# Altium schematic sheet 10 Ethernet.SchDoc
size 386 x 246 mm
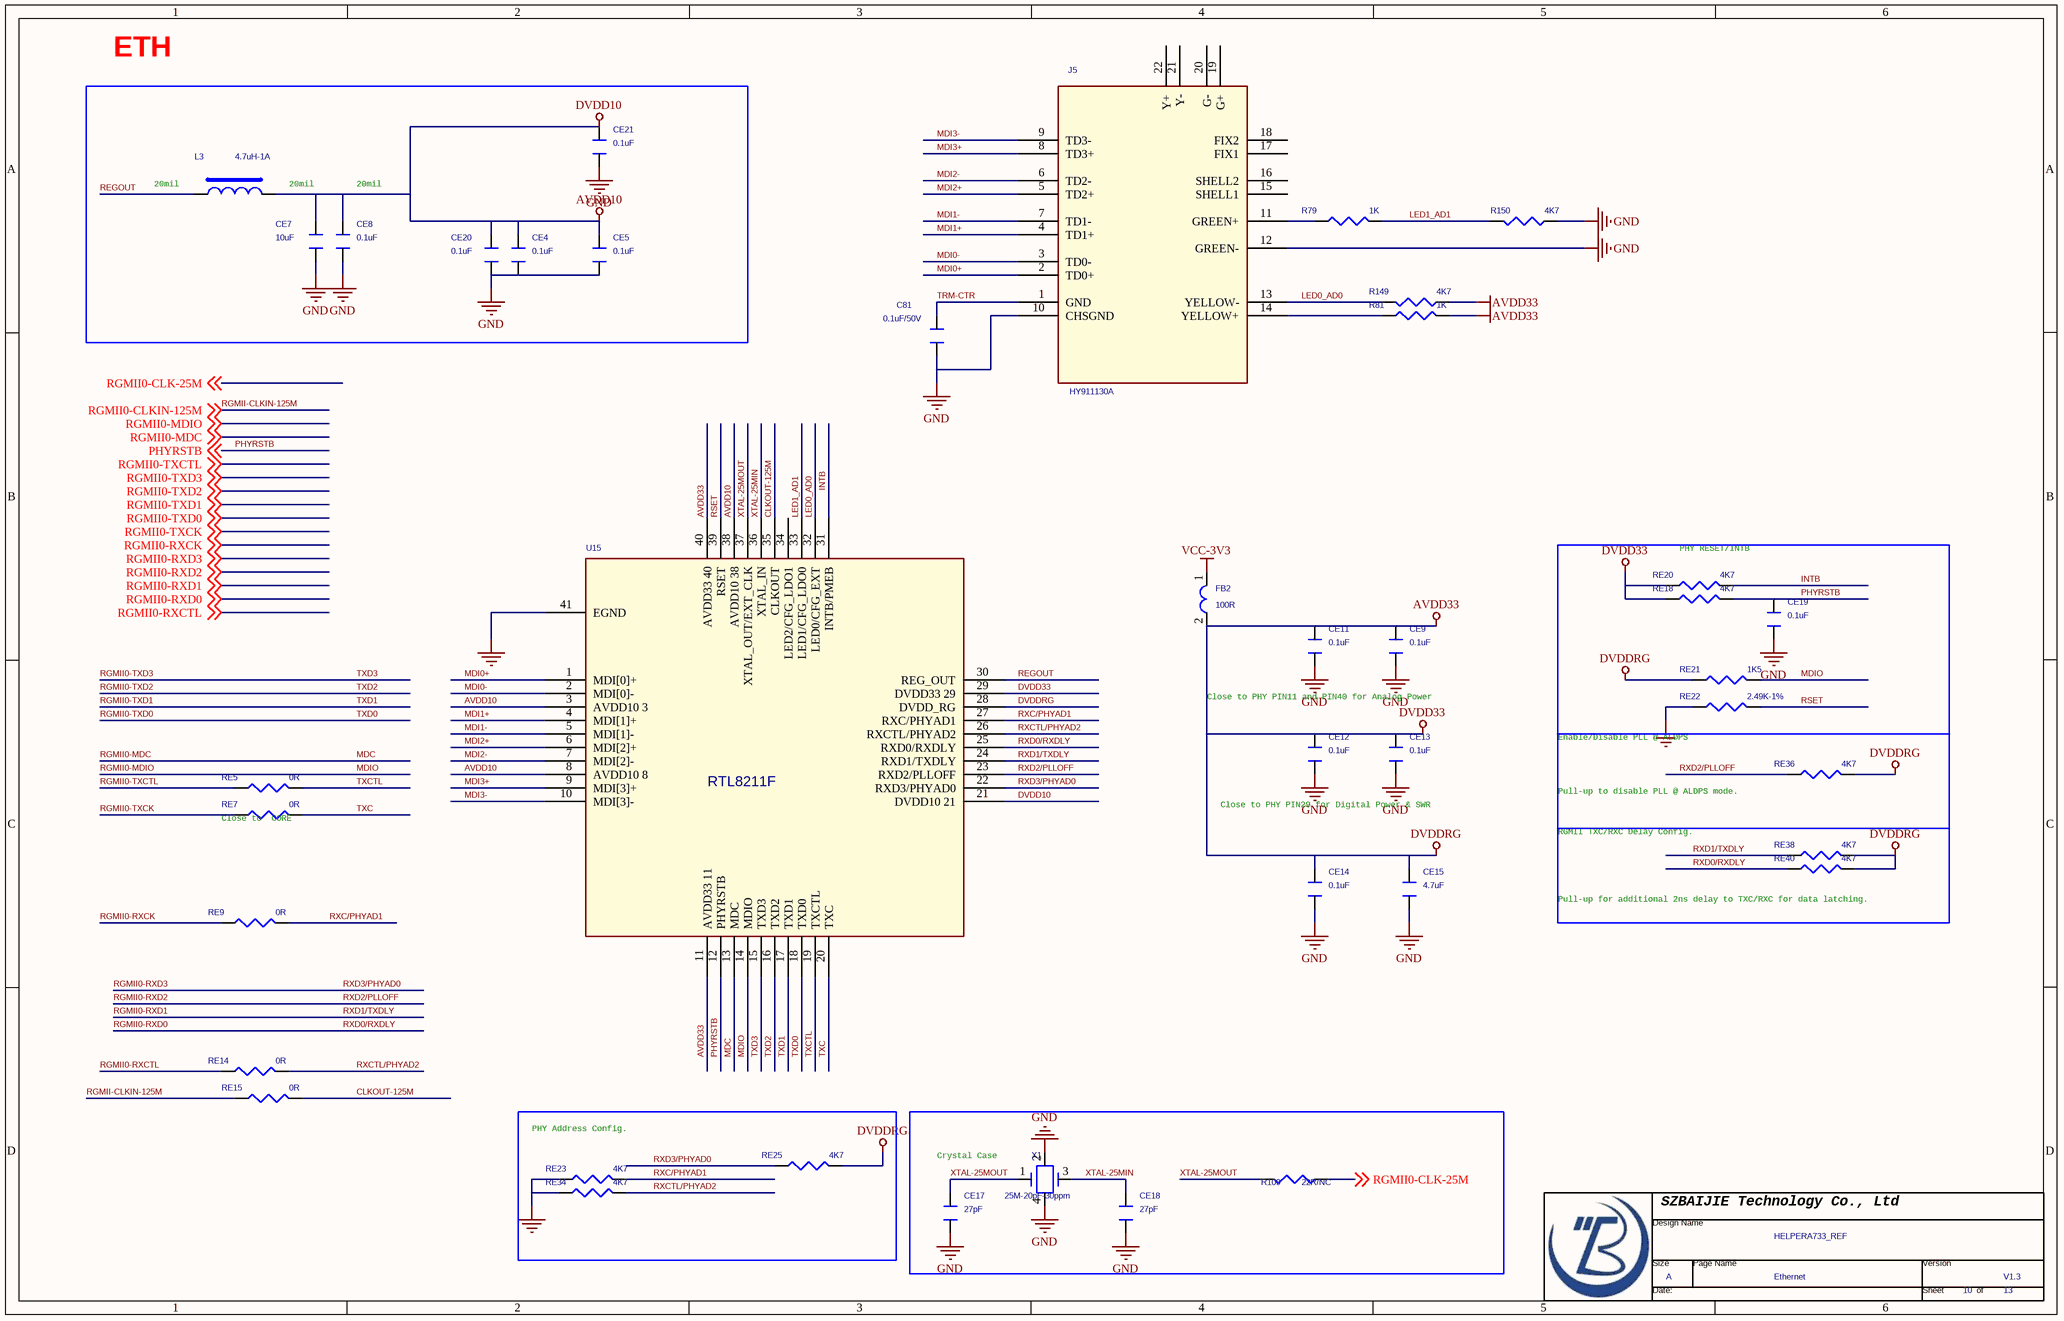
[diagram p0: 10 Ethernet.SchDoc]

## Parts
*  Page Count: 13  Page Number: 10  Page Size: A  Title: HELPERA733_REF  RevCode: V1.3  Doc: Ethernet  (hidden comment: TitleBlock0-BJ)  (graphical)
C81  0.1uF/50V  [C0402]
CE4  0.1uF  [C0402]
CE5  0.1uF  [C0402]
CE7  10uF  [C0402]
CE8  0.1uF  [C0402]
CE9  0.1uF  [C0402]
CE11  0.1uF  [C0402]
CE12  0.1uF  [C0402]
CE13  0.1uF  [C0402]
CE14  0.1uF  [C0402]
CE15  4.7uF  [C0402]
CE17  27pF  [C0402]
CE18  27pF  [C0402]
CE19  0.1uF  [C0402]
CE20  0.1uF  [C0402]
CE21  0.1uF  [C0402]
FB2  100R  [L0603]
J5  HY911130A  [HY911130A]
L3  4.7uH-1A  [LP160_200H100]
R79  1K  [R0402]
R81  1K  [R0402]
R109  22R/NC  [R0402]
R149  4K7  [R0402]
R150  4K7  [R0402]
RE5  0R  [R0402]
RE7  0R  [R0402]
RE9  0R  [R0402]
RE14  0R  [R0402]
RE15  0R  [R0402]
RE18  4K7  [R0402]
RE20  4K7  [R0402]
RE21  1K5  [R0402]
RE22  2.49K-1%  [R0402]
RE23  4K7  [R0402]
RE25  4K7  [R0402]
RE34  4K7  [R0402]
RE36  4K7  [R0402]
RE38  4K7  [R0402]
RE40  4K7  [R0402]
U15  RTL8211F  [QFN40]
X1  25M-20pF-30ppm  [X3225]

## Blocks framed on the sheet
PHY RESET/INTB: CE19 RE18 RE20-RE22
RGMII TXC/RXC Delay Config.: RE38 RE40
PHY Address Config.: RE23 RE25 RE34
Crystal Case: CE17 CE18 R109 X1

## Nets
AVDD10: CE4.2 CE5.2 CE7.2 CE8.2 CE20.2 CE21.2 L3.2 U15.3(AVDD10_3) U15.8(AVDD10_8) U15.21(DVDD10_21) U15.38(AVDD10_38)  [also labelled DVDD10]
AVDD33: CE9.2 CE11.2 CE12.2 CE13.2 CE14.2 CE15.2 FB2.2 R81.2 R149.1 RE18.1 RE20.1 RE21.1 RE25.2 RE36.2 RE38.2 RE40.2 U15.11(AVDD33_11) U15.28(DVDD_RG) U15.29(DVDD33_29) U15.40(AVDD33_40)  [also labelled DVDD33, DVDDRG]
GND: C81.1 CE4.1 CE5.1 CE7.1 CE8.1 CE9.1 CE11.1 CE12.1 CE13.1 CE14.1 CE15.1 CE17.1 CE18.1 CE19.1 CE20.1 CE21.1 J5.10(CHSGND) J5.12(GREEN-) R150.1 RE22.1 RE23.1 RE34.1 U15.41(EGND) X1.2 X1.4
VCC-3V3: FB2.1
CLKOUT-125M: RE15.2 U15.35(CLKOUT)
INTB: RE20.2 U15.31(INTB/PMEB)
LED0_AD0: J5.13(YELLOW-) R149.2 U15.32(LED0/CFG_EXT)
LED1_AD1: R79.2 R150.2 U15.33(LED1/CFG_LDO0)
MDC: U15.13(MDC) ; off-sheet RGMII0-MDC  [also labelled RGMII0-MDC]
MDI0+: J5.2(TD0+) U15.1(MDI[0]+)
MDI0-: J5.3(TD0-) U15.2(MDI[0]-)
MDI1+: J5.4(TD1+) U15.4(MDI[1]+)
MDI1-: J5.7(TD1-) U15.5(MDI[1]-)
MDI2+: J5.5(TD2+) U15.6(MDI[2]+)
MDI2-: J5.6(TD2-) U15.7(MDI[2]-)
MDI3+: J5.8(TD3+) U15.9(MDI[3]+)
MDI3-: J5.9(TD3-) U15.10(MDI[3]-)
MDIO: RE21.2 U15.14(MDIO) ; off-sheet RGMII0-MDIO  [also labelled RGMII0-MDIO]
PHYRSTB: CE19.2 RE18.2 U15.12(PHYRSTB) ; off-sheet PHYRSTB
REGOUT: L3.1 U15.30(REG_OUT)
RGMII0-CLK-25M: R109.1 ; off-sheet RGMII0-CLK-25M
RGMII0-RXCK: RE9.1 ; off-sheet RGMII0-RXCK
RGMII0-RXCTL: RE14.1 ; off-sheet RGMII0-RXCTL
RGMII0-RXD0: RE40.1 U15.25(RXD0/RXDLY) ; off-sheet RGMII0-RXD0  [also labelled RXD0/RXDLY]
RGMII0-RXD1: RE38.1 U15.24(RXD1/TXDLY) ; off-sheet RGMII0-RXD1  [also labelled RXD1/TXDLY]
RGMII0-RXD2: RE36.1 U15.23(RXD2/PLLOFF) ; off-sheet RGMII0-RXD2  [also labelled RXD2/PLLOFF]
RGMII0-RXD3: RE25.1 U15.22(RXD3/PHYAD0) ; off-sheet RGMII0-RXD3  [also labelled RXD3/PHYAD0]
RGMII0-TXCK: RE7.1 ; off-sheet RGMII0-TXCK
RGMII0-TXCTL: RE5.1 ; off-sheet RGMII0-TXCTL
RGMII0-TXD0: U15.18(TXD0) ; off-sheet RGMII0-TXD0  [also labelled TXD0]
RGMII0-TXD1: U15.17(TXD1) ; off-sheet RGMII0-TXD1  [also labelled TXD1]
RGMII0-TXD2: U15.16(TXD2) ; off-sheet RGMII0-TXD2  [also labelled TXD2]
RGMII0-TXD3: U15.15(TXD3) ; off-sheet RGMII0-TXD3  [also labelled TXD3]
RGMII-CLKIN-125M: RE15.1 ; off-sheet RGMII0-CLKIN-125M  [also labelled RGMII0-CLKIN-125M]
RSET: RE22.2 U15.39(RSET)
RXC/PHYAD1: RE9.2 RE23.2 U15.27(RXC/PHYAD1)
RXCTL/PHYAD2: RE14.2 RE34.2 U15.26(RXCTL/PHYAD2)
TRM-CTR: C81.2 J5.1(GND)
TXC: RE7.2 U15.20(TXC)
TXCTL: RE5.2 U15.19(TXCTL)
XTAL-25MIN: CE18.2 U15.36(XTAL_IN) X1.3
XTAL-25MOUT: CE17.2 R109.2 U15.37(XTAL_OUT/EXT_CLK) X1.1
NetJ5_11: J5.11(GREEN+) R79.1
NetJ5_14: J5.14(YELLOW+) R81.1

Not connected (* = marked no-connect by the designer): J5 15(SHELL1) 16(SHELL2) 17(FIX1) 18(FIX2) 19(G+) 20(G-) 21(Y-) 22(Y+); U15 34(LED2/CFG_LDO1)

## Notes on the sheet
- ETH
- (near L3) 20mil
- 20mil
- Close to PHY PIN11 and PIN40 for Analog Power
- Pull-up to disable PLL @ ALDPS mode.
- Enable/Disable PLL @ ALDPS
- (near RE7) Close to  CORE
- Close to PHY PIN29 for Digital Power & SWR
- Pull-up for additional 2ns delay to TXC/RXC for data latching.

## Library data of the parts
C81 = CAPACITOR_0_Dup1
CE4 CE5 CE7-CE9 CE11-CE15 CE17-CE21 = C-C0402_Dup2
FB2 = INDUCTOR_0_Dup1: RoHS BEAD/600ohm 100Mhz Z=600Ω DCR<0.2Ω 800mA SMT L0603; OriginalSymbolOrigin: (10,0); Pin Names Rotate: TRUE; Pin Names Visible: FALSE
L3 = L-L2016
R79 R81 R109 R149 R150 = R_Dup5
RE5 RE7 RE9 RE14 RE15 RE18 RE20-RE23 RE25 RE34 RE36 RE38 RE40 = R-R0402-5%_Dup4
U15 = 8211F: ID: OT-IC0192
X1 = 3224: ID: CR-S-P0019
